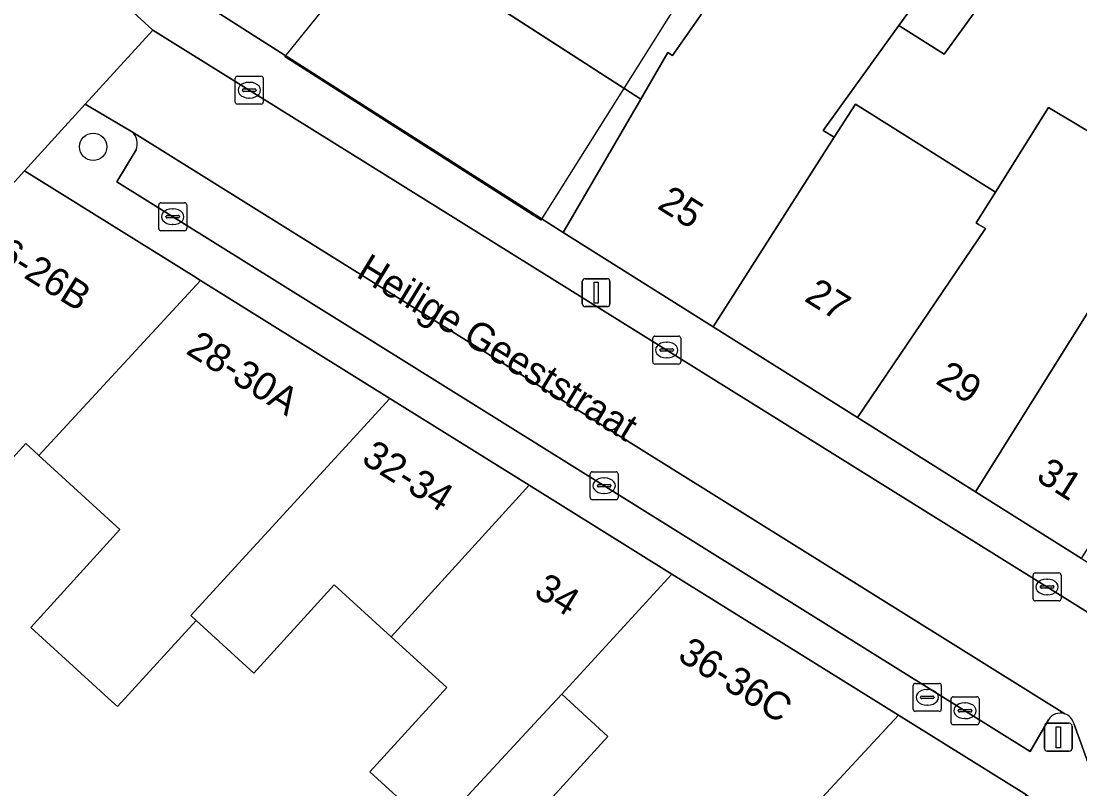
# Model space of a CAD drawing. Extents: x 160663 to 161506, y 382245 to 383291.
# Drawn here: x 160958.95 to 160996.83, y 383120.11 to 383147.58 of the extents above; entities that cross this region are included whole.
import ezdxf

# ---------------------------------------------------------------- set-up
doc = ezdxf.new("R2010")
doc.units = 0
for name, color, linetype in [('IMGEO_Boom', 7, 'Continuous'), ('IMGEO_Brandkraan', 7, 'Continuous'), ('IMGEO_Erf', 7, 'Continuous'), ('IMGEO_Hek', 7, 'Continuous'), ('IMGEO_Kolk', 7, 'Continuous'), ('IMGEO_Lichtmast', 7, 'Continuous'), ('IMGEO_Openbare_ruimte_label', 7, 'Continuous'), ('IMGEO_Pand', 7, 'Continuous'), ('IMGEO_Pand_nummerreeks', 7, 'Continuous'), ('IMGEO_Pand_vergunning_verleend', 7, 'Continuous'), ('IMGEO_Parkeervlak_open', 7, 'Continuous'), ('IMGEO_Rijbaan_lokaal_open', 7, 'Continuous'), ('IMGEO_Voetpad_open', 7, 'Continuous')]:
    doc.layers.add(name, color=color, linetype=linetype)

msp = doc.modelspace()

# ---------------------------------------------------------------- linework, layer by layer
at = {"layer": 'IMGEO_Boom'}
msp.add_circle((160961.528, 383143.09), 0.489, dxfattribs=at)
at = {"layer": 'IMGEO_Brandkraan'}
for p, q in [((160990.875, 383122.961), (160990.875, 383123.813)), ((160990.95, 383123.887), (160991.802, 383123.887)), ((160991.876, 383123.813), (160991.876, 383122.961)), ((160991.134, 383123.381), (160991.134, 383123.393)), ((160991.177, 383123.43), (160991.575, 383123.43)), ((160991.363, 383123.667), (160991.388, 383123.667)), ((160991.618, 383123.393), (160991.618, 383123.381)), ((160991.572, 383123.344), (160991.174, 383123.344)), ((160991.386, 383123.107), (160991.361, 383123.107)), ((160991.802, 383122.887), (160990.95, 383122.887))]:
    msp.add_line(p, q, dxfattribs=at)
for points in [[(160990.875, 383122.961), (160990.875, 383123.813)], [(160990.95, 383123.887), (160991.802, 383123.887)], [(160991.876, 383123.813), (160991.876, 383122.961)], [(160991.802, 383122.887), (160990.95, 383122.887)]]:
    msp.add_lwpolyline(points, dxfattribs=at)
for centre, radius, start, end in [((160990.952, 383123.811), 0.0765, 91.552, 178.448), ((160990.952, 383123.811), 0.0765, 91.552, 178.448), ((160991.8, 383123.811), 0.0765, 1.552, 88.448), ((160991.8, 383123.811), 0.0765, 1.552, 88.448), ((160991.174, 383123.39), 0.0403, 85.8775, 175.7526), ((160991.171, 383123.38), 0.0366, 178.938, 274.7102), ((160991.575, 383123.387), 0.043, 264.8664, 352.4533), ((160991.579, 383123.392), 0.0386, 1.7309, 96.639), ((160990.952, 383122.963), 0.0765, 181.552, 268.448), ((160990.952, 383122.963), 0.0765, 181.552, 268.448), ((160991.8, 383122.963), 0.0765, 271.552, 358.448), ((160991.8, 383122.963), 0.0765, 271.552, 358.448)]:
    msp.add_arc(centre, radius, start, end, dxfattribs=at)
for centre, major_axis, ratio, start_param, end_param in [((160991.362, 383123.387), (-0.387, 0.002), 0.722429, 4.712389, 7.853982), ((160991.387, 383123.387), (-0.39, 0.002), 0.717154, 1.570796, 4.712389)]:
    msp.add_ellipse(centre, major_axis=major_axis, ratio=ratio, start_param=start_param, end_param=end_param, dxfattribs=at)
at = {"layer": 'IMGEO_Erf'}
for points in [[(160969.257, 383152.457), (160981.122, 383144.798), (160982.092, 383146.468), (160982.261, 383146.361), (160987.44, 383153.764)], [(160994.219, 383149.504), (160991.982, 383146.405), (160990.36, 383147.424), (160987.654, 383143.676), (160988.043, 383143.432), (160988.801, 383144.618), (160989.835, 383143.968), (160993.812, 383141.469), (160995.716, 383144.495), (160997.671, 383143.323)], [(160975.148, 383116.727), (160979.942, 383121.982), (160978.298, 383123.505), (160977.622, 383122.768), (160973.756, 383118.596), (160971.427, 383120.722), (160974.178, 383123.736), (160972.189, 383125.552), (160970.155, 383127.408), (160967.279, 383124.256), (160965.211, 383126.142), (160962.396, 383123.057), (160962.2, 383123.236), (160959.291, 383125.89), (160962.486, 383129.391), (160959.585, 383132.038), (160959.4, 383132.207), (160959.111, 383132.471), (160956.576, 383129.694)]]:
    msp.add_lwpolyline(points, dxfattribs=at)
at = {"layer": 'IMGEO_Hek'}
msp.add_lwpolyline([(160968.817, 383152.741), (160981.122, 383144.798)], dxfattribs=at)
at = {"layer": 'IMGEO_Kolk'}
for p, q in [((160966.613, 383144.688), (160966.613, 383145.54)), ((160966.688, 383145.614), (160967.54, 383145.614)), ((160967.101, 383145.394), (160967.126, 383145.394)), ((160967.614, 383145.54), (160967.614, 383144.688)), ((160966.872, 383145.108), (160966.872, 383145.12)), ((160967.31, 383145.071), (160966.912, 383145.071)), ((160966.915, 383145.157), (160967.313, 383145.157)), ((160967.356, 383145.12), (160967.356, 383145.108)), ((160967.54, 383144.614), (160966.688, 383144.614)), ((160967.124, 383144.834), (160967.099, 383144.834)), ((160963.872, 383140.16), (160963.872, 383141.012)), ((160963.947, 383141.086), (160964.799, 383141.086)), ((160964.36, 383140.866), (160964.385, 383140.866)), ((160964.873, 383141.012), (160964.873, 383140.16)), ((160964.131, 383140.58), (160964.131, 383140.592)), ((160964.569, 383140.543), (160964.171, 383140.543)), ((160964.174, 383140.629), (160964.572, 383140.629)), ((160964.615, 383140.592), (160964.615, 383140.58)), ((160964.799, 383140.086), (160963.947, 383140.086)), ((160964.383, 383140.306), (160964.358, 383140.306)), ((160981.626, 383136.315), (160982.478, 383136.315)), ((160981.551, 383135.389), (160981.551, 383136.241)), ((160982.039, 383136.095), (160982.064, 383136.095)), ((160982.552, 383136.241), (160982.552, 383135.389)), ((160981.81, 383135.809), (160981.81, 383135.821)), ((160982.248, 383135.772), (160981.85, 383135.772)), ((160981.853, 383135.858), (160982.251, 383135.858)), ((160982.062, 383135.535), (160982.037, 383135.535)), ((160982.294, 383135.821), (160982.294, 383135.809)), ((160982.478, 383135.315), (160981.626, 383135.315)), ((160979.311, 383130.533), (160979.311, 383131.385)), ((160979.386, 383131.459), (160980.238, 383131.459)), ((160980.312, 383131.385), (160980.312, 383130.533)), ((160979.57, 383130.953), (160979.57, 383130.965)), ((160979.613, 383131.002), (160980.011, 383131.002)), ((160979.799, 383131.239), (160979.824, 383131.239)), ((160980.054, 383130.965), (160980.054, 383130.953)), ((160980.008, 383130.916), (160979.61, 383130.916)), ((160979.822, 383130.679), (160979.797, 383130.679)), ((160980.238, 383130.459), (160979.386, 383130.459)), ((160995.161, 383126.913), (160995.161, 383127.765)), ((160995.236, 383127.839), (160996.088, 383127.839)), ((160995.649, 383127.619), (160995.674, 383127.619)), ((160996.162, 383127.765), (160996.162, 383126.913)), ((160995.42, 383127.333), (160995.42, 383127.345)), ((160995.858, 383127.296), (160995.46, 383127.296)), ((160995.463, 383127.382), (160995.861, 383127.382)), ((160995.904, 383127.345), (160995.904, 383127.333)), ((160996.088, 383126.839), (160995.236, 383126.839)), ((160995.672, 383127.059), (160995.647, 383127.059)), ((160992.3, 383123.406), (160993.152, 383123.406)), ((160992.225, 383122.48), (160992.225, 383123.332)), ((160992.713, 383123.186), (160992.738, 383123.186)), ((160993.226, 383123.332), (160993.226, 383122.48)), ((160992.484, 383122.9), (160992.484, 383122.912)), ((160992.922, 383122.863), (160992.524, 383122.863)), ((160992.527, 383122.949), (160992.925, 383122.949)), ((160992.736, 383122.626), (160992.711, 383122.626)), ((160992.968, 383122.912), (160992.968, 383122.9)), ((160993.152, 383122.406), (160992.3, 383122.406))]:
    msp.add_line(p, q, dxfattribs=at)
for points in [[(160966.613, 383144.688), (160966.613, 383145.54)], [(160966.688, 383145.614), (160967.54, 383145.614)], [(160967.614, 383145.54), (160967.614, 383144.688)], [(160967.54, 383144.614), (160966.688, 383144.614)], [(160963.872, 383140.16), (160963.872, 383141.012)], [(160963.947, 383141.086), (160964.799, 383141.086)], [(160964.873, 383141.012), (160964.873, 383140.16)], [(160964.799, 383140.086), (160963.947, 383140.086)], [(160981.626, 383136.315), (160982.478, 383136.315)], [(160981.551, 383135.389), (160981.551, 383136.241)], [(160982.552, 383136.241), (160982.552, 383135.389)], [(160982.478, 383135.315), (160981.626, 383135.315)], [(160979.311, 383130.533), (160979.311, 383131.385)], [(160979.386, 383131.459), (160980.238, 383131.459)], [(160980.312, 383131.385), (160980.312, 383130.533)], [(160980.238, 383130.459), (160979.386, 383130.459)], [(160995.161, 383126.913), (160995.161, 383127.765)], [(160995.236, 383127.839), (160996.088, 383127.839)], [(160996.162, 383127.765), (160996.162, 383126.913)], [(160996.088, 383126.839), (160995.236, 383126.839)], [(160992.3, 383123.406), (160993.152, 383123.406)], [(160992.225, 383122.48), (160992.225, 383123.332)], [(160993.226, 383123.332), (160993.226, 383122.48)], [(160993.152, 383122.406), (160992.3, 383122.406)]]:
    msp.add_lwpolyline(points, dxfattribs=at)
for centre, radius, start, end in [((160966.69, 383145.538), 0.0765, 91.552, 178.448), ((160966.69, 383145.538), 0.0765, 91.552, 178.448), ((160967.538, 383145.538), 0.0765, 1.552, 88.448), ((160967.538, 383145.538), 0.0765, 1.552, 88.448), ((160966.912, 383145.117), 0.0403, 85.8775, 175.7526), ((160966.909, 383145.107), 0.0366, 178.938, 274.7102), ((160967.313, 383145.114), 0.043, 264.8664, 352.4533), ((160967.317, 383145.119), 0.0386, 1.7309, 96.639), ((160966.69, 383144.69), 0.0765, 181.552, 268.448), ((160966.69, 383144.69), 0.0765, 181.552, 268.448), ((160967.538, 383144.69), 0.0765, 271.552, 358.448), ((160967.538, 383144.69), 0.0765, 271.552, 358.448), ((160963.949, 383141.01), 0.0765, 91.552, 178.448), ((160963.949, 383141.01), 0.0765, 91.552, 178.448), ((160964.797, 383141.01), 0.0765, 1.552, 88.448), ((160964.797, 383141.01), 0.0765, 1.552, 88.448), ((160964.171, 383140.589), 0.0403, 85.8775, 175.7526), ((160964.168, 383140.579), 0.0366, 178.938, 274.7102), ((160964.572, 383140.586), 0.043, 264.8664, 352.4533), ((160964.576, 383140.591), 0.0386, 1.7309, 96.639), ((160963.949, 383140.162), 0.0765, 181.552, 268.448), ((160963.949, 383140.162), 0.0765, 181.552, 268.448), ((160964.797, 383140.162), 0.0765, 271.552, 358.448), ((160964.797, 383140.162), 0.0765, 271.552, 358.448), ((160981.628, 383136.239), 0.0765, 91.552, 178.448), ((160981.628, 383136.239), 0.0765, 91.552, 178.448), ((160982.476, 383136.239), 0.0765, 1.552, 88.448), ((160982.476, 383136.239), 0.0765, 1.552, 88.448), ((160981.85, 383135.818), 0.0403, 85.8775, 175.7526), ((160981.847, 383135.808), 0.0366, 178.938, 274.7102), ((160982.251, 383135.815), 0.043, 264.8664, 352.4533), ((160982.255, 383135.82), 0.0386, 1.7309, 96.639), ((160981.628, 383135.391), 0.0765, 181.552, 268.448), ((160981.628, 383135.391), 0.0765, 181.552, 268.448), ((160982.476, 383135.391), 0.0765, 271.552, 358.448), ((160982.476, 383135.391), 0.0765, 271.552, 358.448), ((160979.388, 383131.383), 0.0765, 91.552, 178.448), ((160979.388, 383131.383), 0.0765, 91.552, 178.448), ((160980.236, 383131.383), 0.0765, 1.552, 88.448), ((160980.236, 383131.383), 0.0765, 1.552, 88.448), ((160979.61, 383130.962), 0.0403, 85.8775, 175.7526), ((160979.607, 383130.952), 0.0366, 178.938, 274.7102), ((160980.011, 383130.959), 0.043, 264.8664, 352.4533), ((160980.015, 383130.964), 0.0386, 1.7309, 96.639), ((160979.388, 383130.535), 0.0765, 181.552, 268.448), ((160979.388, 383130.535), 0.0765, 181.552, 268.448), ((160980.236, 383130.535), 0.0765, 271.552, 358.448), ((160980.236, 383130.535), 0.0765, 271.552, 358.448), ((160995.238, 383127.763), 0.0765, 91.552, 178.448), ((160995.238, 383127.763), 0.0765, 91.552, 178.448), ((160996.086, 383127.763), 0.0765, 1.552, 88.448), ((160996.086, 383127.763), 0.0765, 1.552, 88.448), ((160995.46, 383127.342), 0.0403, 85.8775, 175.7526), ((160995.457, 383127.332), 0.0366, 178.938, 274.7102), ((160995.861, 383127.339), 0.043, 264.8664, 352.4533), ((160995.865, 383127.344), 0.0386, 1.7309, 96.639), ((160995.238, 383126.915), 0.0765, 181.552, 268.448), ((160995.238, 383126.915), 0.0765, 181.552, 268.448), ((160996.086, 383126.915), 0.0765, 271.552, 358.448), ((160996.086, 383126.915), 0.0765, 271.552, 358.448), ((160992.302, 383123.33), 0.0765, 91.552, 178.448), ((160992.302, 383123.33), 0.0765, 91.552, 178.448), ((160993.15, 383123.33), 0.0765, 1.552, 88.448), ((160993.15, 383123.33), 0.0765, 1.552, 88.448), ((160992.524, 383122.909), 0.0403, 85.8775, 175.7526), ((160992.521, 383122.899), 0.0366, 178.938, 274.7102), ((160992.925, 383122.906), 0.043, 264.8664, 352.4533), ((160992.929, 383122.911), 0.0386, 1.7309, 96.639), ((160992.302, 383122.482), 0.0765, 181.552, 268.448), ((160992.302, 383122.482), 0.0765, 181.552, 268.448), ((160993.15, 383122.482), 0.0765, 271.552, 358.448), ((160993.15, 383122.482), 0.0765, 271.552, 358.448)]:
    msp.add_arc(centre, radius, start, end, dxfattribs=at)
for centre, major_axis, ratio, start_param, end_param in [((160967.1, 383145.114), (-0.387, 0.002), 0.722429, 4.712389, 7.853982), ((160967.125, 383145.114), (-0.39, 0.002), 0.717154, 1.570796, 4.712389), ((160964.359, 383140.586), (-0.387, 0.002), 0.722429, 4.712389, 7.853982), ((160964.384, 383140.586), (-0.39, 0.002), 0.717154, 1.570796, 4.712389), ((160982.038, 383135.815), (-0.387, 0.002), 0.722429, 4.712389, 7.853982), ((160982.063, 383135.815), (-0.39, 0.002), 0.717154, 1.570796, 4.712389), ((160979.798, 383130.959), (-0.387, 0.002), 0.722429, 4.712389, 7.853982), ((160979.823, 383130.959), (-0.39, 0.002), 0.717154, 1.570796, 4.712389), ((160995.648, 383127.339), (-0.387, 0.002), 0.722429, 4.712389, 7.853982), ((160995.673, 383127.339), (-0.39, 0.002), 0.717154, 1.570796, 4.712389), ((160992.712, 383122.906), (-0.387, 0.002), 0.722429, 4.712389, 7.853982), ((160992.737, 383122.906), (-0.39, 0.002), 0.717154, 1.570796, 4.712389)]:
    msp.add_ellipse(centre, major_axis=major_axis, ratio=ratio, start_param=start_param, end_param=end_param, dxfattribs=at)
at = {"layer": 'IMGEO_Lichtmast'}
for p, q in [((160979.029, 383137.469), (160979.029, 383138.269)), ((160979.029, 383138.269), (160979.029, 383137.469)), ((160979.129, 383138.369), (160979.919, 383138.369)), ((160979.919, 383138.369), (160979.129, 383138.369)), ((160980.019, 383138.269), (160980.019, 383137.469)), ((160980.019, 383137.469), (160980.019, 383138.269)), ((160979.919, 383137.369), (160979.129, 383137.369)), ((160979.129, 383137.369), (160979.919, 383137.369)), ((160995.568, 383121.561), (160995.568, 383122.361)), ((160995.568, 383122.361), (160995.568, 383121.561)), ((160995.668, 383122.461), (160996.458, 383122.461)), ((160996.458, 383122.461), (160995.668, 383122.461)), ((160996.558, 383122.361), (160996.558, 383121.561)), ((160996.558, 383121.561), (160996.558, 383122.361)), ((160996.458, 383121.461), (160995.668, 383121.461)), ((160995.668, 383121.461), (160996.458, 383121.461))]:
    msp.add_line(p, q, dxfattribs=at)
for points in [[(160979.449, 383138.244), (160979.599, 383138.244), (160979.599, 383137.494), (160979.449, 383137.494), (160979.449, 383138.244)], [(160995.988, 383122.336), (160996.138, 383122.336), (160996.138, 383121.586), (160995.988, 383121.586), (160995.988, 383122.336)]]:
    msp.add_lwpolyline(points, dxfattribs=at)
for centre, start, end in [((160979.129, 383138.269), 90, 180), ((160979.129, 383138.269), 90, 180), ((160979.919, 383138.269), 0, 90), ((160979.919, 383138.269), 360, 90), ((160979.129, 383137.469), 180, 270), ((160979.129, 383137.469), 180, 270), ((160979.919, 383137.469), 270, 0), ((160979.919, 383137.469), 270, 0), ((160995.668, 383122.361), 90, 180), ((160995.668, 383122.361), 90, 180), ((160996.458, 383122.361), 0, 90), ((160996.458, 383122.361), 360, 90), ((160995.668, 383121.561), 180, 270), ((160995.668, 383121.561), 180, 270), ((160996.458, 383121.561), 270, 0), ((160996.458, 383121.561), 270, 0)]:
    msp.add_arc(centre, 0.1, start, end, dxfattribs=at)
at = {"layer": 'IMGEO_Pand'}
for points in [[(160990.36, 383147.424), (160992.597, 383150.523), (160987.44, 383153.764), (160982.261, 383146.361), (160982.092, 383146.468), (160981.122, 383144.798), (160978.347, 383140.023), (160983.71, 383136.649), (160988.043, 383143.432), (160987.654, 383143.676)], [(160992.597, 383150.523), (160990.36, 383147.424), (160991.982, 383146.405), (160994.219, 383149.504)], [(160993.453, 383140.16), (160993.211, 383140.312), (160993.12, 383140.369), (160993.812, 383141.469), (160989.835, 383143.968), (160988.801, 383144.618), (160988.043, 383143.432), (160983.71, 383136.649), (160988.875, 383133.4)], [(160997.174, 383137.254), (160997.666, 383136.918), (160999.126, 383139.09), (160999.354, 383138.903), (161000.933, 383141.367), (161000, 383141.927), (160997.671, 383143.323), (160995.716, 383144.495), (160993.812, 383141.469), (160993.12, 383140.369), (160993.211, 383140.312), (160993.453, 383140.16), (160988.875, 383133.4), (160993.102, 383130.741)], [(160965.366, 383138.305), (160965.124, 383138.456), (160959.063, 383142.231), (160950.889, 383133.202), (160956.576, 383129.694), (160959.111, 383132.471), (160959.4, 383132.207), (160959.585, 383132.038)], [(161000.994, 383134.955), (161000, 383135.597), (160999.801, 383135.725), (161000, 383136.043), (160999.828, 383136.153), (161000, 383136.45), (161000.794, 383137.82), (161002.115, 383137.066), (161003.642, 383139.743), (161002.492, 383140.433), (161000.933, 383141.367), (160999.354, 383138.903), (160999.126, 383139.09), (160997.666, 383136.918), (160997.174, 383137.254), (160993.102, 383130.741), (160996.894, 383128.356)], [(160972.148, 383134.082), (160965.366, 383138.305), (160959.585, 383132.038), (160962.486, 383129.391), (160959.291, 383125.89), (160962.2, 383123.236), (160962.396, 383123.057), (160965.211, 383126.142), (160965.023, 383126.314)], [(160970.155, 383127.408), (160972.189, 383125.552), (160977.131, 383130.978), (160972.148, 383134.082), (160965.023, 383126.314), (160965.211, 383126.142), (160967.279, 383124.256)], [(160982.237, 383127.799), (160977.131, 383130.978), (160972.189, 383125.552), (160974.178, 383123.736), (160971.427, 383120.722), (160973.756, 383118.596), (160977.622, 383122.768), (160978.298, 383123.505)], [(160990.343, 383122.744), (160982.237, 383127.799), (160978.298, 383123.505), (160979.942, 383121.982), (160975.148, 383116.727), (160980.441, 383111.897), (160980.854, 383112.349), (160981.109, 383112.629), (160984.179, 383116.092), (160984.288, 383116.215)], [(160994.931, 383119.893), (160990.343, 383122.744), (160984.288, 383116.215), (160984.179, 383116.092), (160987.458, 383114.051), (160984.829, 383109.829), (160987.878, 383108.228), (160988.28, 383108.017), (160990.767, 383112.011), (160990.386, 383112.249), (160990.488, 383112.413), (160990.366, 383112.525)]]:
    msp.add_lwpolyline(points, close=True, dxfattribs=at)
at = {"layer": 'IMGEO_Pand_vergunning_verleend'}
msp.add_lwpolyline([(160968.386, 383146.308), (160975.04, 383154.548), (160983.129, 383149.333), (160977.542, 383140.461)], close=True, dxfattribs=at)
at = {"layer": 'IMGEO_Parkeervlak_open'}
msp.add_lwpolyline([(160969.257, 383152.457), (160965.864, 383148.271), (160965.706, 383148.076), (160978.347, 383140.023), (160981.122, 383144.798)], close=True, dxfattribs=at)
for points in [[(160996.295, 383122.798), (160962.901, 383143.638)], [(160963.061, 383142.98), (160962.368, 383141.835), (160995.054, 383121.453), (160995.715, 383122.584)]]:
    msp.add_lwpolyline(points, dxfattribs=at)
for centre, radius, start, end in [((160962.534, 383143.2), 0.572, 337.3391, 49.9947), ((160996.138, 383122.33), 0.493, 71.4545, 149.0501)]:
    msp.add_arc(centre, radius, start, end, dxfattribs=at)
at = {"layer": 'IMGEO_Rijbaan_lokaal_open'}
for points in [[(160963.665, 383147.263), (160961.243, 383144.612)], [(160999.105, 383125.196), (160963.665, 383147.263)], [(160961.243, 383144.612), (160962.901, 383143.638)], [(160962.901, 383143.638), (160996.295, 383122.798)], [(160996.614, 383122.457), (160997.385, 383120.334)]]:
    msp.add_lwpolyline(points, dxfattribs=at)
msp.add_arc((160996.141, 383122.335), 0.488, 14.5265, 71.6552, dxfattribs=at)
at = {"layer": 'IMGEO_Voetpad_open'}
for points in [[(161029.88, 383105.049), (161035.38, 383101.904), (161036.787, 383104.325), (161036.411, 383104.597), (161019.927, 383114.345), (161000.192, 383125.94), (161000.349, 383126.208), (161000, 383126.414), (160999.324, 383126.814), (160996.923, 383128.337), (160996.894, 383128.356), (160993.102, 383130.741), (160988.875, 383133.4), (160983.71, 383136.649), (160978.347, 383140.023), (160965.706, 383148.076), (160959.844, 383151.624), (160959.492, 383151.837), (160952.683, 383156.759), (160947.835, 383160.473), (160943.238, 383164.738), (160938.66, 383168.986), (160934.055, 383173.259), (160929.271, 383177.698)], [(160951.104, 383156.083), (160958.418, 383150.922), (160958.997, 383151.541), (160963.665, 383147.263), (160999.105, 383125.196)], [(160950.889, 383133.202), (160959.063, 383142.231), (160961.243, 383144.612), (160963.665, 383147.263), (160958.997, 383151.541), (160958.418, 383150.922)], [(160962.901, 383143.638), (160961.243, 383144.612), (160959.063, 383142.231), (160965.124, 383138.456), (160965.366, 383138.305), (160972.148, 383134.082), (160977.131, 383130.978), (160982.237, 383127.799), (160990.343, 383122.744), (160994.931, 383119.893), (160999.48, 383117.061), (161000, 383116.737), (161004.038, 383114.222), (161008.588, 383111.389), (161013.121, 383108.566), (161017.705, 383105.712), (161022.475, 383102.741), (161025.226, 383101.166), (161026.056, 383100.781), (161031.892, 383097.822), (161037.593, 383094.932), (161043.206, 383092.086)], [(160962.368, 383141.835), (160963.061, 383142.98)], [(160995.715, 383122.584), (160995.054, 383121.453), (160962.368, 383141.835)], [(160997.385, 383120.334), (160996.614, 383122.457)]]:
    msp.add_lwpolyline(points, dxfattribs=at)
for centre, radius, start, end in [((160962.534, 383143.2), 0.572, 337.3391, 49.9947), ((160996.138, 383122.33), 0.493, 71.4545, 149.0501), ((160996.141, 383122.335), 0.488, 14.5265, 71.6552)]:
    msp.add_arc(centre, radius, start, end, dxfattribs=at)

# ---------------------------------------------------------------- texts
at = {"layer": 'IMGEO_Openbare_ruimte_label'}
msp.add_text('Heilige Geeststraat', height=1, rotation=328.5351, dxfattribs=at).set_placement((160970.901, 383138.456))
at = {"layer": 'IMGEO_Pand_nummerreeks'}
for s, rotation, p in [('25', 327.8284, (160981.671, 383140.909)), ('26-26B', 328.0839, (160957.365, 383139.447)), ('27', 327.8284, (160986.935, 383137.597)), ('28-30A', 328.092, (160964.803, 383135.711)), ('29', 327.8284, (160991.631, 383134.643)), ('32-34', 328.0805, (160971.083, 383131.8)), ('31', 327.8227, (160995.226, 383131.177)), ('34', 328.0863, (160977.248, 383127.042)), ('36-36C', 328.0519, (160982.395, 383124.754))]:
    msp.add_text(s, height=1, rotation=rotation, dxfattribs=at).set_placement(p)

doc.saveas('drawing.dxf')
